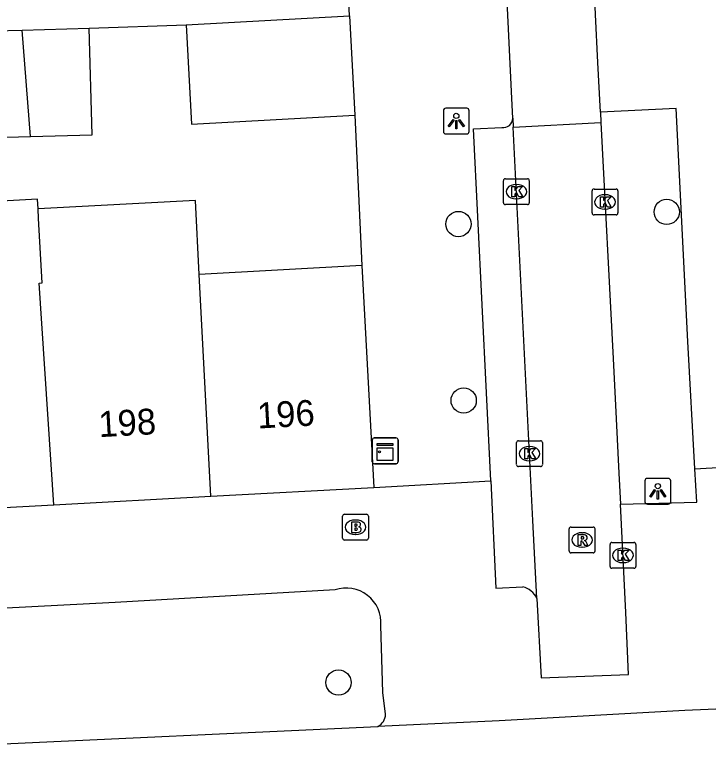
# Model space of a CAD drawing. Extents: x 162250 to 162654, y 380744 to 381605.
# Drawn here: x 162473.87 to 162500.72, y 380767.31 to 380795.64 of the extents above; entities that cross this region are included whole.
import ezdxf

# ---------------------------------------------------------------- set-up
doc = ezdxf.new("R2010")
doc.units = 0
for name, color, linetype in [('IMGEO_Boom', 7, 'Continuous'), ('IMGEO_Brandkraan', 7, 'Continuous'), ('IMGEO_Fietspad_open', 7, 'Continuous'), ('IMGEO_Kast', 7, 'Continuous'), ('IMGEO_Kolk', 7, 'Continuous'), ('IMGEO_Lichtpunt', 7, 'Continuous'), ('IMGEO_Muur', 7, 'Continuous'), ('IMGEO_Pand', 7, 'Continuous'), ('IMGEO_Pand_nummerreeks', 7, 'Continuous'), ('IMGEO_Rijbaan_lokaal_open', 7, 'Continuous'), ('IMGEO_Rioolput', 7, 'Continuous'), ('IMGEO_Voetpad_open', 7, 'Continuous')]:
    doc.layers.add(name, color=color, linetype=linetype)

msp = doc.modelspace()

# ---------------------------------------------------------------- linework, layer by layer
at = {"layer": 'IMGEO_Boom'}
for centre in [(162499.112, 380788), (162491.051, 380787.531), (162491.254, 380780.7), (162486.409, 380769.779)]:
    msp.add_circle(centre, 0.489, dxfattribs=at)
at = {"layer": 'IMGEO_Brandkraan'}
for p, q in [((162486.564, 380775.367), (162486.564, 380776.219)), ((162486.639, 380776.293), (162487.491, 380776.293)), ((162487.052, 380776.073), (162487.077, 380776.073)), ((162487.565, 380776.219), (162487.565, 380775.367)), ((162487.075, 380775.513), (162487.05, 380775.513)), ((162487.491, 380775.293), (162486.639, 380775.293))]:
    msp.add_line(p, q, dxfattribs=at)
for points in [[(162486.564, 380775.367), (162486.564, 380776.219)], [(162486.639, 380776.293), (162487.491, 380776.293)], [(162487.565, 380776.219), (162487.565, 380775.367)], [(162486.912, 380775.993), (162486.912, 380775.593), (162487.125, 380775.593)], [(162487.143, 380775.993), (162486.912, 380775.993)], [(162487.091, 380775.912), (162487.037, 380775.912), (162487.037, 380775.836)], [(162487.037, 380775.836), (162487.09, 380775.836)], [(162487.099, 380775.76), (162487.037, 380775.76), (162487.037, 380775.679)], [(162487.037, 380775.679), (162487.099, 380775.679)], [(162487.491, 380775.293), (162486.639, 380775.293)]]:
    msp.add_lwpolyline(points, dxfattribs=at)
for centre, radius, start, end in [((162486.641, 380776.217), 0.0765, 91.552, 178.448), ((162486.641, 380776.217), 0.0765, 91.552, 178.448), ((162487.489, 380776.217), 0.0765, 1.552, 88.448), ((162487.489, 380776.217), 0.0765, 1.552, 88.448), ((162487.092, 380775.874), 0.0379, 267.8285, 90.9355), ((162487.1, 380775.719), 0.0404, 269.8759, 90.5077), ((162487.147, 380775.848), 0.145, 59.4692, 91.5367), ((162487.172, 380775.895), 0.0922, 285.5137, 58.1501), ((162487.177, 380775.703), 0.105, 301.3115, 78.989), ((162487.131, 380775.844), 0.251, 268.6676, 293.5347), ((162486.641, 380775.369), 0.0765, 181.552, 268.448), ((162486.641, 380775.369), 0.0765, 181.552, 268.448), ((162487.489, 380775.369), 0.0765, 271.552, 358.448), ((162487.489, 380775.369), 0.0765, 271.552, 358.448)]:
    msp.add_arc(centre, radius, start, end, dxfattribs=at)
for centre, major_axis, ratio, start_param, end_param in [((162487.051, 380775.793), (-0.387, 0.002), 0.722429, 4.712389, 7.853982), ((162487.076, 380775.793), (-0.39, 0.002), 0.717154, 1.570796, 4.712389)]:
    msp.add_ellipse(centre, major_axis=major_axis, ratio=ratio, start_param=start_param, end_param=end_param, dxfattribs=at)
at = {"layer": 'IMGEO_Fietspad_open'}
for points in [[(162502.821, 380768.833), (162499.808, 380768.701), (162492.632, 380768.294), (162487.935, 380768.078)], [(162466.113, 380767.309), (162469.412, 380767.47), (162472.316, 380767.359), (162487.935, 380768.078)]]:
    msp.add_lwpolyline(points, dxfattribs=at)
at = {"layer": 'IMGEO_Kast'}
for p, q in [((162487.715, 380778.325), (162487.715, 380779.166)), ((162487.715, 380779.166), (162487.715, 380778.325)), ((162487.79, 380779.25), (162488.631, 380779.25)), ((162488.631, 380779.25), (162487.79, 380779.25)), ((162488.715, 380779.175), (162488.715, 380778.334)), ((162488.715, 380778.334), (162488.715, 380779.175)), ((162488.64, 380778.25), (162487.799, 380778.25)), ((162487.799, 380778.25), (162488.64, 380778.25))]:
    msp.add_line(p, q, dxfattribs=at)
for points in [[(162487.91, 380779.04), (162488.51, 380779.04), (162488.51, 380778.955), (162487.91, 380778.955), (162487.91, 380779.04)], [(162487.91, 380778.865), (162488.51, 380778.865), (162488.51, 380778.376), (162487.91, 380778.376), (162487.91, 380778.865)]]:
    msp.add_lwpolyline(points, dxfattribs=at)
msp.add_circle((162487.994, 380778.714), 0.0377, dxfattribs=at)
for centre, start, end in [((162487.793, 380779.172), 92.4484, 184.2845), ((162487.793, 380779.172), 92.4484, 184.2845), ((162488.637, 380779.172), 2.4484, 94.2845), ((162488.637, 380779.172), 2.4484, 94.2845), ((162487.793, 380778.328), 182.4484, 274.2845), ((162487.793, 380778.328), 182.4484, 274.2845), ((162488.637, 380778.328), 272.4484, 4.2845), ((162488.637, 380778.328), 272.4484, 4.2845)]:
    msp.add_arc(centre, 0.0779, start, end, dxfattribs=at)
at = {"layer": 'IMGEO_Kolk'}
for p, q in [((162492.792, 380788.358), (162492.792, 380789.21)), ((162492.867, 380789.284), (162493.719, 380789.284)), ((162493.793, 380789.21), (162493.793, 380788.358)), ((162493.28, 380789.064), (162493.305, 380789.064)), ((162496.223, 380787.961), (162496.223, 380788.813)), ((162496.298, 380788.887), (162497.15, 380788.887)), ((162497.224, 380788.813), (162497.224, 380787.961)), ((162493.303, 380788.504), (162493.278, 380788.504)), ((162496.711, 380788.667), (162496.736, 380788.667)), ((162493.719, 380788.284), (162492.867, 380788.284)), ((162496.734, 380788.107), (162496.709, 380788.107)), ((162497.15, 380787.887), (162496.298, 380787.887)), ((162493.298, 380778.215), (162493.298, 380779.067)), ((162493.373, 380779.141), (162494.225, 380779.141)), ((162493.786, 380778.921), (162493.811, 380778.921)), ((162494.299, 380779.067), (162494.299, 380778.215)), ((162493.809, 380778.361), (162493.784, 380778.361)), ((162494.225, 380778.141), (162493.373, 380778.141)), ((162496.993, 380775.202), (162497.845, 380775.202)), ((162496.918, 380774.276), (162496.918, 380775.128)), ((162497.406, 380774.982), (162497.431, 380774.982)), ((162497.919, 380775.128), (162497.919, 380774.276)), ((162497.429, 380774.422), (162497.404, 380774.422)), ((162497.845, 380774.202), (162496.993, 380774.202))]:
    msp.add_line(p, q, dxfattribs=at)
for points in [[(162492.792, 380788.358), (162492.792, 380789.21)], [(162492.867, 380789.284), (162493.719, 380789.284)], [(162493.793, 380789.21), (162493.793, 380788.358)], [(162493.113, 380788.984), (162493.236, 380788.984), (162493.236, 380788.833), (162493.366, 380788.984), (162493.53, 380788.984), (162493.384, 380788.833), (162493.537, 380788.584), (162493.385, 380788.584), (162493.3, 380788.748), (162493.236, 380788.681), (162493.236, 380788.584), (162493.113, 380788.584), (162493.113, 380788.984)], [(162496.223, 380787.961), (162496.223, 380788.813)], [(162496.298, 380788.887), (162497.15, 380788.887)], [(162497.224, 380788.813), (162497.224, 380787.961)], [(162496.544, 380788.587), (162496.667, 380788.587), (162496.667, 380788.436), (162496.797, 380788.587), (162496.961, 380788.587), (162496.815, 380788.436), (162496.968, 380788.187), (162496.816, 380788.187), (162496.731, 380788.351), (162496.667, 380788.284), (162496.667, 380788.187), (162496.544, 380788.187), (162496.544, 380788.587)], [(162493.719, 380788.284), (162492.867, 380788.284)], [(162497.15, 380787.887), (162496.298, 380787.887)], [(162493.298, 380778.215), (162493.298, 380779.067)], [(162493.373, 380779.141), (162494.225, 380779.141)], [(162494.299, 380779.067), (162494.299, 380778.215)], [(162493.619, 380778.841), (162493.742, 380778.841), (162493.742, 380778.69), (162493.872, 380778.841), (162494.036, 380778.841), (162493.89, 380778.69), (162494.043, 380778.441), (162493.891, 380778.441), (162493.806, 380778.605), (162493.742, 380778.538), (162493.742, 380778.441), (162493.619, 380778.441), (162493.619, 380778.841)], [(162494.225, 380778.141), (162493.373, 380778.141)], [(162496.993, 380775.202), (162497.845, 380775.202)], [(162496.918, 380774.276), (162496.918, 380775.128)], [(162497.919, 380775.128), (162497.919, 380774.276)], [(162497.239, 380774.902), (162497.362, 380774.902), (162497.362, 380774.751), (162497.492, 380774.902), (162497.656, 380774.902), (162497.51, 380774.751), (162497.663, 380774.502), (162497.511, 380774.502), (162497.426, 380774.666), (162497.362, 380774.599), (162497.362, 380774.502), (162497.239, 380774.502), (162497.239, 380774.902)], [(162497.845, 380774.202), (162496.993, 380774.202)]]:
    msp.add_lwpolyline(points, dxfattribs=at)
for centre, start, end in [((162492.869, 380789.208), 91.552, 178.448), ((162492.869, 380789.208), 91.552, 178.448), ((162493.717, 380789.208), 1.552, 88.448), ((162493.717, 380789.208), 1.552, 88.448), ((162496.3, 380788.811), 91.552, 178.448), ((162496.3, 380788.811), 91.552, 178.448), ((162497.148, 380788.811), 1.552, 88.448), ((162497.148, 380788.811), 1.552, 88.448), ((162492.869, 380788.36), 181.552, 268.448), ((162492.869, 380788.36), 181.552, 268.448), ((162493.717, 380788.36), 271.552, 358.448), ((162493.717, 380788.36), 271.552, 358.448), ((162496.3, 380787.963), 181.552, 268.448), ((162496.3, 380787.963), 181.552, 268.448), ((162497.148, 380787.963), 271.552, 358.448), ((162497.148, 380787.963), 271.552, 358.448), ((162493.375, 380779.065), 91.552, 178.448), ((162493.375, 380779.065), 91.552, 178.448), ((162494.223, 380779.065), 1.552, 88.448), ((162494.223, 380779.065), 1.552, 88.448), ((162493.375, 380778.217), 181.552, 268.448), ((162493.375, 380778.217), 181.552, 268.448), ((162494.223, 380778.217), 271.552, 358.448), ((162494.223, 380778.217), 271.552, 358.448), ((162496.995, 380775.126), 91.552, 178.448), ((162496.995, 380775.126), 91.552, 178.448), ((162497.843, 380775.126), 1.552, 88.448), ((162497.843, 380775.126), 1.552, 88.448), ((162496.995, 380774.278), 181.552, 268.448), ((162496.995, 380774.278), 181.552, 268.448), ((162497.843, 380774.278), 271.552, 358.448), ((162497.843, 380774.278), 271.552, 358.448)]:
    msp.add_arc(centre, 0.0765, start, end, dxfattribs=at)
for centre, major_axis, ratio, start_param, end_param in [((162493.279, 380788.784), (-0.387, 0.002), 0.722429, 4.712389, 7.853982), ((162493.304, 380788.784), (-0.39, 0.002), 0.717154, 1.570796, 4.712389), ((162496.71, 380788.387), (-0.387, 0.002), 0.722429, 4.712389, 7.853982), ((162496.735, 380788.387), (-0.39, 0.002), 0.717154, 1.570796, 4.712389), ((162493.785, 380778.641), (-0.387, 0.002), 0.722429, 4.712389, 7.853982), ((162493.81, 380778.641), (-0.39, 0.002), 0.717154, 1.570796, 4.712389), ((162497.405, 380774.702), (-0.387, 0.002), 0.722429, 4.712389, 7.853982), ((162497.43, 380774.702), (-0.39, 0.002), 0.717154, 1.570796, 4.712389)]:
    msp.add_ellipse(centre, major_axis=major_axis, ratio=ratio, start_param=start_param, end_param=end_param, dxfattribs=at)
at = {"layer": 'IMGEO_Lichtpunt'}
for p, q in [((162490.47, 380791.92), (162490.47, 380791.113)), ((162490.47, 380791.92), (162490.47, 380791.113)), ((162491.372, 380792.015), (162490.564, 380792.015)), ((162491.372, 380792.015), (162490.564, 380792.015)), ((162491.466, 380791.113), (162491.466, 380791.92)), ((162491.466, 380791.113), (162491.466, 380791.92)), ((162490.564, 380791.019), (162491.372, 380791.019)), ((162490.564, 380791.019), (162491.372, 380791.019)), ((162498.27, 380777.587), (162498.27, 380776.78)), ((162498.27, 380777.587), (162498.27, 380776.78)), ((162499.172, 380777.682), (162498.364, 380777.682)), ((162499.172, 380777.682), (162498.364, 380777.682)), ((162499.266, 380776.78), (162499.266, 380777.587)), ((162499.266, 380776.78), (162499.266, 380777.587)), ((162498.364, 380776.686), (162499.172, 380776.686)), ((162498.364, 380776.686), (162499.172, 380776.686))]:
    msp.add_line(p, q, dxfattribs=at)
for points in [[(162490.844, 380791.584), (162490.883, 380791.556), (162490.695, 380791.294), (162490.657, 380791.321), (162490.844, 380791.584)], [(162490.946, 380791.536), (162490.993, 380791.536), (162490.993, 380791.214), (162490.946, 380791.214), (162490.946, 380791.536)], [(162491.056, 380791.556), (162491.094, 380791.583), (162491.281, 380791.321), (162491.242, 380791.293), (162491.056, 380791.556)], [(162498.644, 380777.251), (162498.683, 380777.223), (162498.495, 380776.961), (162498.457, 380776.988), (162498.644, 380777.251)], [(162498.746, 380777.203), (162498.793, 380777.203), (162498.793, 380776.881), (162498.746, 380776.881), (162498.746, 380777.203)], [(162498.856, 380777.223), (162498.894, 380777.25), (162499.081, 380776.988), (162499.042, 380776.96), (162498.856, 380777.223)]]:
    msp.add_lwpolyline(points, dxfattribs=at)
for centre in [(162490.969, 380791.718), (162498.769, 380777.385)]:
    msp.add_circle(centre, 0.0994, dxfattribs=at)
for centre, start, end in [((162490.564, 380791.92), 90, 180), ((162490.564, 380791.92), 90, 180), ((162491.372, 380791.92), 0, 90), ((162491.372, 380791.92), 0, 90), ((162490.564, 380791.113), 180, 270), ((162490.564, 380791.113), 180, 270), ((162491.372, 380791.113), 270, 0), ((162491.372, 380791.113), 270, 360), ((162498.364, 380777.587), 90, 180), ((162498.364, 380777.587), 90, 180), ((162499.172, 380777.587), 0, 90), ((162499.172, 380777.587), 0, 90), ((162498.364, 380776.78), 180, 270), ((162498.364, 380776.78), 180, 270), ((162499.172, 380776.78), 270, 0), ((162499.172, 380776.78), 270, 360)]:
    msp.add_arc(centre, 0.0946, start, end, dxfattribs=at)
at = {"layer": 'IMGEO_Muur'}
msp.add_lwpolyline([(162487.044, 380791.747), (162487.308, 380785.923)], dxfattribs=at)
at = {"layer": 'IMGEO_Pand'}
for points in [[(162480.508, 380795.245), (162486.836, 380795.589)], [(162486.836, 380795.589), (162487.044, 380791.747)], [(162472.005, 380794.982), (162474.167, 380795.042)], [(162474.167, 380795.042), (162476.762, 380795.115)], [(162474.49, 380790.919), (162474.167, 380795.042)], [(162474.49, 380790.919), (162476.877, 380790.986), (162476.762, 380795.115)], [(162480.508, 380795.245), (162480.717, 380791.403), (162487.044, 380791.747)], [(162472.005, 380794.982), (162472.12, 380790.853), (162474.49, 380790.919)], [(162474.783, 380788.123), (162474.764, 380788.493), (162468.465, 380788.151), (162468.715, 380784.912)], [(162481.017, 380785.581), (162480.868, 380788.44), (162474.783, 380788.123)], [(162475.394, 380776.66), (162474.818, 380785.244), (162474.933, 380785.25), (162474.803, 380787.742), (162474.783, 380788.123)], [(162487.308, 380785.923), (162481.017, 380785.581)], [(162487.308, 380785.923), (162487.775, 380777.333)], [(162481.465, 380776.99), (162481.017, 380785.581)], [(162481.465, 380776.99), (162487.775, 380777.333)], [(162475.394, 380776.66), (162481.465, 380776.99)], [(162469.376, 380776.333), (162475.394, 380776.66)]]:
    msp.add_lwpolyline(points, dxfattribs=at)
at = {"layer": 'IMGEO_Rijbaan_lokaal_open'}
for points in [[(162496.544, 380791.858), (162496.445, 380793.785), (162496.36, 380795.645), (162496.225, 380798.581)], [(162493.151, 380791.628), (162493.113, 380792.395), (162492.838, 380798.329)], [(162493.151, 380791.628), (162493.169, 380791.275)], [(162496.544, 380791.858), (162496.565, 380791.459)], [(162493.169, 380791.275), (162496.565, 380791.459)], [(162496.565, 380791.459), (162497.034, 380782.324), (162497.151, 380779.995), (162497.257, 380777.88), (162497.317, 380776.685)], [(162494.089, 380773.04), (162493.929, 380776.055), (162493.169, 380791.275)], [(162494.089, 380773.04), (162494.252, 380769.964), (162497.631, 380770.094), (162497.528, 380772.494), (162497.317, 380776.685)]]:
    msp.add_lwpolyline(points, dxfattribs=at)
at = {"layer": 'IMGEO_Rioolput'}
for p, q in [((162495.41, 380775.8), (162496.262, 380775.8)), ((162495.335, 380774.874), (162495.335, 380775.726)), ((162495.823, 380775.58), (162495.848, 380775.58)), ((162496.336, 380775.726), (162496.336, 380774.874)), ((162495.846, 380775.02), (162495.821, 380775.02)), ((162496.262, 380774.8), (162495.41, 380774.8))]:
    msp.add_line(p, q, dxfattribs=at)
for points in [[(162495.41, 380775.8), (162496.262, 380775.8)], [(162495.335, 380774.874), (162495.335, 380775.726)], [(162495.924, 380775.498), (162495.672, 380775.5), (162495.672, 380775.1)], [(162496.336, 380775.726), (162496.336, 380774.874)], [(162495.672, 380775.1), (162495.796, 380775.1), (162495.796, 380775.262), (162495.807, 380775.262)], [(162495.85, 380775.419), (162495.796, 380775.419), (162495.796, 380775.338)], [(162495.796, 380775.338), (162495.848, 380775.338)], [(162495.854, 380775.233), (162495.925, 380775.1), (162496.065, 380775.1), (162496, 380775.226)], [(162496.262, 380774.8), (162495.41, 380774.8)]]:
    msp.add_lwpolyline(points, dxfattribs=at)
for centre, radius, start, end in [((162495.412, 380775.724), 0.0765, 91.552, 178.448), ((162495.412, 380775.724), 0.0765, 91.552, 178.448), ((162496.26, 380775.724), 0.0765, 1.552, 88.448), ((162496.26, 380775.724), 0.0765, 1.552, 88.448), ((162495.923, 380775.388), 0.109, 350.3612, 89.416), ((162495.806, 380775.209), 0.0533, 26.0293, 88.6989), ((162495.832, 380775.527), 0.19, 274.7715, 282.9687), ((162495.856, 380775.323), 0.0964, 77.0061, 93.1865), ((162495.87, 380775.38), 0.0378, 276.6634, 79.6772), ((162495.921, 380775.388), 0.112, 277.5842, 350.9817), ((162495.905, 380775.173), 0.108, 29.5134, 73.7905), ((162495.412, 380774.876), 0.0765, 181.552, 268.448), ((162495.412, 380774.876), 0.0765, 181.552, 268.448), ((162496.26, 380774.876), 0.0765, 271.552, 358.448), ((162496.26, 380774.876), 0.0765, 271.552, 358.448)]:
    msp.add_arc(centre, radius, start, end, dxfattribs=at)
for centre, major_axis, ratio, start_param, end_param in [((162495.822, 380775.3), (-0.387, 0.002), 0.722429, 4.712389, 7.853982), ((162495.847, 380775.3), (-0.39, 0.002), 0.717154, 1.570796, 4.712389)]:
    msp.add_ellipse(centre, major_axis=major_axis, ratio=ratio, start_param=start_param, end_param=end_param, dxfattribs=at)
at = {"layer": 'IMGEO_Voetpad_open'}
for points in [[(162486.836, 380795.589), (162486.74, 380797.501)], [(162476.762, 380795.115), (162480.508, 380795.245)], [(162500.205, 380778.05), (162499.931, 380782.983), (162499.481, 380792.01), (162496.544, 380791.858)], [(162487.044, 380791.747), (162487.308, 380785.923)], [(162492.299, 380777.594), (162491.633, 380791.217), (162492.725, 380791.274)], [(162497.317, 380776.685), (162500.277, 380776.758), (162500.205, 380778.05)], [(162500.205, 380778.05), (162502.201, 380778.165)], [(162487.775, 380777.333), (162492.299, 380777.594)], [(162492.299, 380777.594), (162492.503, 380773.432), (162493.545, 380773.489)], [(162486.276, 380773.368), (162477.761, 380772.884), (162465.837, 380772.261), (162466.099, 380767.579), (162466.113, 380767.309)], [(162488.232, 380768.552), (162488.125, 380769.392), (162488.052, 380771.992)]]:
    msp.add_lwpolyline(points, dxfattribs=at)
for centre, radius, start, end in [((162492.791, 380791.628), 0.36, 259.4489, 0.0033), ((162493.328, 380772.672), 0.845, 25.8083, 75.1214), ((162486.705, 380772.087), 1.35, 355.9477, 108.517), ((162487.665, 380768.577), 0.568, 298.4155, 357.4434)]:
    msp.add_arc(centre, radius, start, end, dxfattribs=at)

# ---------------------------------------------------------------- texts
at = {"layer": 'IMGEO_Pand_nummerreeks'}
for s, rotation, p in [('196', 3.1106, (162483.281, 380779.613)), ('198', 3.1112, (162477.142, 380779.279))]:
    msp.add_text(s, height=1, rotation=rotation, dxfattribs=at).set_placement(p)

doc.saveas('drawing.dxf')
